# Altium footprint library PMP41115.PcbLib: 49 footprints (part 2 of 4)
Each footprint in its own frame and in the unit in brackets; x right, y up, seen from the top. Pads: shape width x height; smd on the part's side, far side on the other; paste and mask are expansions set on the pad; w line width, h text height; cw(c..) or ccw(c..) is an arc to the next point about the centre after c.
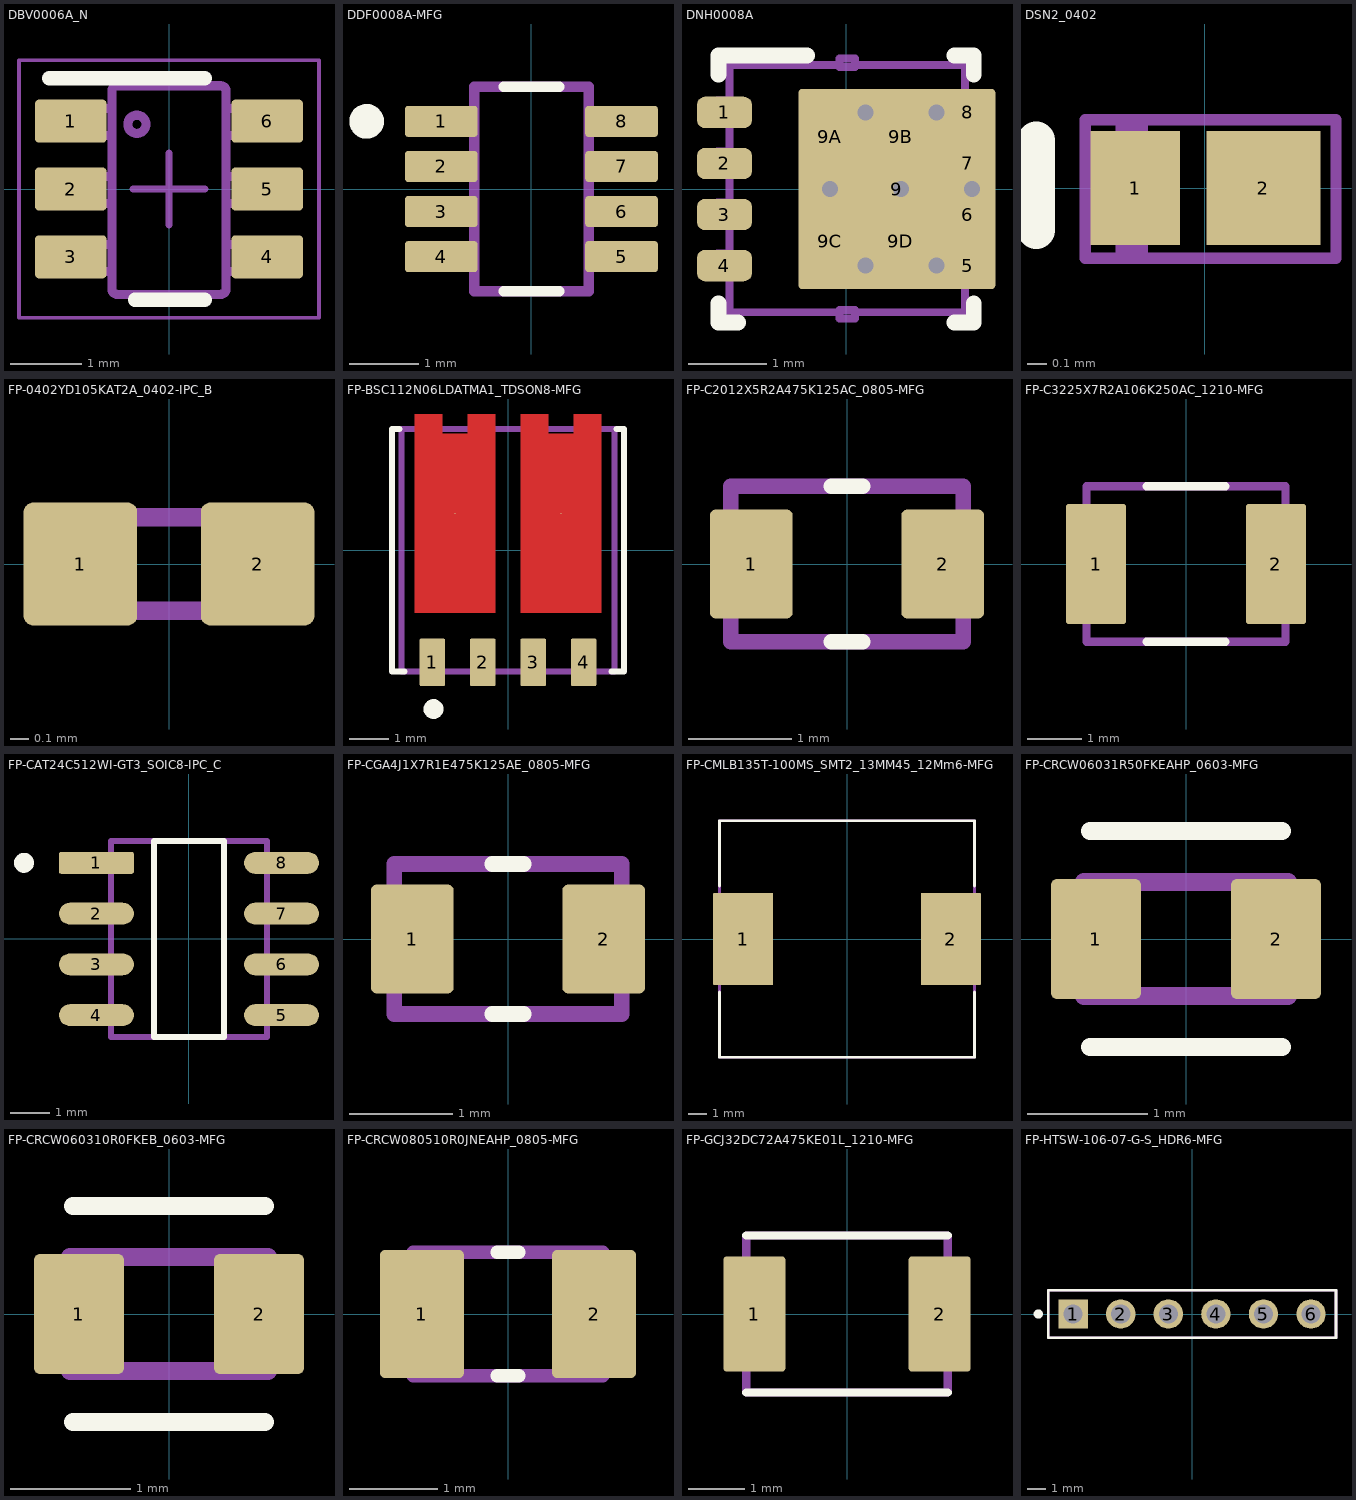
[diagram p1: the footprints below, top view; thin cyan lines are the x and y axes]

## DBV0006A_N [mm] "SOT23, 6-Leads, Body 2.9x1.6mm, Pitch 0.95mm, Lead Span 2.8mm, IPC Medium Density"
height 1.45
pads (6):
  rrect17% 1x0.6 smd: 1(-1.375,0.95) 2(-1.375,0) 3(-1.375,-0.95) 4(1.375,-0.95) 5(1.375,0) 6(1.375,0.95)
Top Overlay:
  lines w0.2: -1.675,1.55 0.5,1.55 ; -0.475,-1.55 0.5,-1.55
Mechanical 5:
  lines w0.127: 0.724,-1.475 ccw(c0.723,-1.399) 0.8,-1.399 0.8,1.37 ccw(c0.723,1.37) 0.724,1.446 ; 0.723,-1.475 -0.724,-1.475 -0.725,-1.475 cw(c-0.724,-1.399) -0.801,-1.399 -0.801,1.37 cw(c-0.724,1.37) -0.725,1.446 -0.724,1.446 0.723,1.446 ; 0.723,-1.475 0.724,-1.475 ; 0.723,1.446 0.724,1.446 ; -1.423,-1.154 -1.423,-0.78 -1.206,-0.78 -1.113,-0.78 -1.081,-0.78 -0.828,-0.78 -0.801,-0.78 -0.801,-1.154 -0.828,-1.154 -1.081,-1.154 -1.113,-1.154 -1.206,-1.154 -1.423,-1.154 ; -1.423,-0.202 -1.423,0.173 -1.206,0.173 -1.113,0.173 -1.081,0.173 -0.828,0.173 -0.801,0.173 -0.801,-0.202 -0.828,-0.202 -1.081,-0.202 -1.113,-0.202 -1.206,-0.202 -1.423,-0.202 ; -1.423,0.751 -1.423,1.125 -1.206,1.125 -1.113,1.125 -1.081,1.125 -0.828,1.125 -0.801,1.125 -0.801,0.751 -0.828,0.751 -1.081,0.751 -1.113,0.751 -1.206,0.751 -1.423,0.751 ; -0.577,0.906 ccw(c-0.45,0.906) -0.323,0.906 ccw(c-0.45,0.906) -0.577,0.906 ; 0.8,-1.154 0.8,-0.78 0.827,-0.78 1.08,-0.78 1.112,-0.78 1.205,-0.78 1.422,-0.78 1.422,-1.154 1.205,-1.154 1.112,-1.154 1.08,-1.154 0.827,-1.154 0.8,-1.154 ; 0.8,-0.202 0.8,0.173 0.827,0.173 1.08,0.173 1.112,0.173 1.205,0.173 1.422,0.173 1.422,-0.202 1.205,-0.202 1.112,-0.202 1.08,-0.202 0.827,-0.202 0.8,-0.202 ; 0.8,0.751 0.8,1.125 0.827,1.125 1.08,1.125 1.112,1.125 1.205,1.125 1.422,1.125 1.422,0.751 1.205,0.751 1.112,0.751 1.08,0.751 0.827,0.751 0.8,0.751
  text ".Designator" at -0.075,0.925 h0.51
Mechanical 15:
  lines w0.05: -2.1,-1.8 -2.1,1.8 2.1,1.8 2.1,-1.8 -2.1,-1.8
  lines w0.1: -0.5,0 0.5,0 ; 0,-0.5 0,0.5
3D body "DBV0006A.stp": height 1.12, standoff 0, extent -1.422,-1.461 1.423,1.46

## DDF0008A-MFG [mm]
height 1.1
pads (8):
  rrect22% 1.05x0.45 smd paste+0 mask+0: 1(-1.3,0.975) 2(-1.3,0.325) 3(-1.3,-0.325) 4(-1.3,-0.975) 5(1.3,-0.975) 6(1.3,-0.325) 7(1.3,0.325) 8(1.3,0.975)
Top Overlay:
  circle w0.25: c-2.375,0.975 r0.125
  lines w0.15: -0.4,-1.475 0.4,-1.475 ; -0.4,1.475 0.4,1.475
Mechanical 5:
  lines w0.15: -0.825,-1.475 0.825,-1.475 0.825,1.475 -0.825,1.475 -0.825,-1.475
  text ".Designator" at 0,0 h0.5
3D body "IC_LM74502DDF_SOT23-8.STEP": height 0.25, standoff 0, extent -1.925,-1.725 1.925,1.725

## DNH0008A [mm] "VSONP-8"
height 0.9
pads (13):
  rrect50% 0.7x0.4 smd paste-0.05 mask-0.05: 1(-1.55,0.975) 2(-1.55,0.325) 3(-1.55,-0.325) 4(-1.55,-0.975) 5(1.55,-0.975) 6(1.55,-0.325) 7(1.55,0.325) 8(1.55,0.975)
  rrect4% 2.51x2.55 smd paste-1.5 mask-1.5: 9(0.645,0)
  rrect50% 0.705x1.125 on Top Paste: 9A(-0.208,0.662) 9B(0.697,0.662) 9C(-0.208,-0.663) 9D(0.697,-0.663)
via 0.245,0.975 diameter 0.5 hole 0.2
via 1.15,0.975 diameter 0.5 hole 0.2
via 1.15,-0.975 diameter 0.5 hole 0.2
via 0.245,-0.975 diameter 0.5 hole 0.2
via 0.697,0 diameter 0.5 hole 0.2
via -0.208,0 diameter 0.5 hole 0.2
via 1.602,0 diameter 0.5 hole 0.2
Top Overlay:
  lines w0.2: -1.625,-1.453 -1.625,-1.7 -1.378,-1.7 ; -1.625,1.453 -1.625,1.7 -0.5,1.7 ; 1.378,-1.7 1.625,-1.7 1.625,-1.453 ; 1.378,1.7 1.625,1.7 1.625,1.453
Top Solder:
  region: -0.56,-1.175 -0.56,-1.185 -0.552,-1.203 -0.538,-1.217 -0.52,-1.225 -0.51,-1.225 1.165,-1.225 1.175,-1.225 1.193,-1.217 1.207,-1.203 1.215,-1.185 1.215,-1.175 1.215,-1.125 1.8,-1.125 1.81,-1.125 1.828,-1.117 1.842,-1.103 1.85,-1.085 1.85,-1.075 1.85,-0.875 1.85,-0.865 1.842,-0.847 1.828,-0.833 1.81,-0.825 1.8,-0.825 1.215,-0.825 1.215,-0.475 1.8,-0.475 1.81,-0.475 1.828,-0.467 1.842,-0.453 1.85,-0.435 1.85,-0.425 1.85,-0.225 1.85,-0.215 1.842,-0.197 1.828,-0.183 1.81,-0.175 1.8,-0.175 1.215,-0.175 1.215,0.175 1.8,0.175 1.81,0.175 1.828,0.183 1.842,0.197 1.85,0.215 1.85,0.225 1.85,0.425 1.85,0.435 1.842,0.453 1.828,0.467 1.81,0.475 1.8,0.475 1.215,0.475 1.215,0.825 1.8,0.825 1.81,0.825 1.828,0.833 1.842,0.847 1.85,0.865 1.85,0.875 1.85,1.075 1.85,1.085 1.842,1.103 1.828,1.117 1.81,1.125 1.8,1.125 1.215,1.125 1.215,1.175 1.215,1.185 1.207,1.203 1.193,1.217 1.175,1.225 1.165,1.225 -0.51,1.225 -0.52,1.225 -0.538,1.217 -0.552,1.203 -0.56,1.185 -0.56,1.175
Mechanical 5:
  lines w0.1: -1.487,-1.119 -1.487,-1.569 -0.087,-1.569 ; -1.487,-0.819 -1.487,-0.469 ; -1.487,-0.169 -1.487,0.181 ; -1.487,0.481 -1.487,0.831 ; -1.487,1.131 -1.487,1.581 -0.087,1.581 ; 0.113,-1.569 1.513,-1.569 1.513,-1.119 ; 0.113,1.581 1.513,1.581 1.513,1.131 ; 1.513,-0.819 1.513,-0.469 ; 1.513,-0.169 1.513,0.181 ; 1.513,0.481 1.513,0.831 ; -1.637,-1.119 -1.637,-0.819 -1.461,-0.819 -1.461,-1.119 -1.637,-1.119 ; -1.637,-0.469 -1.637,-0.169 -1.461,-0.169 -1.461,-0.469 -1.637,-0.469 ; -1.637,0.181 -1.461,0.181 -1.461,0.481 -1.637,0.481 -1.637,0.181 ; -1.637,0.831 -1.637,1.131 -1.461,1.131 -1.461,0.831 -1.637,0.831 ; -0.087,-1.649 -0.087,-1.543 0.113,-1.543 0.113,-1.649 -0.087,-1.649 ; -0.087,1.554 0.113,1.554 0.113,1.661 -0.087,1.661 -0.087,1.554 ; 1.486,-1.119 1.486,-0.819 1.663,-0.819 1.663,-1.119 1.486,-1.119 ; 1.486,-0.469 1.486,-0.169 1.663,-0.169 1.663,-0.469 1.486,-0.469 ; 1.486,0.181 1.486,0.481 1.663,0.481 1.663,0.181 1.486,0.181 ; 1.486,0.831 1.486,1.131 1.663,1.131 1.663,0.831 1.486,0.831
  text ".Designator" at -0.725,-0.165 h0.38
3D body "DNH0008A.stp": height 0.91, standoff 0.01, extent -1.65,-1.655 1.65,1.655

## DSN2_0402 [mm] "ON SEMICONDUCTOR"
height 0.31
pads (2):
  rect 0.47x0.6 smd: 1(-0.367,0)
  rect 0.6x0.6 smd: 2(0.308,0)
Top Overlay:
  lines w0.2: -0.89,-0.22 -0.89,0.25
Mechanical 5:
  lines w0.06: -0.44,-0.36 -0.44,0.35 ; -0.38,-0.36 -0.38,0.35 ; -0.33,-0.36 -0.33,0.35 ; -0.63,-0.37 -0.63,0.36 0.69,0.36 0.69,-0.37 -0.63,-0.37
  text ".Designator" at -0.26,-0.13 h0.24
3D body: height 0.32, standoff 0.31, extent -0.349,-0.299 -0.221,0.299
3D body: height 0.31, standoff 0, extent -0.499,-0.299 0.499,0.299

## FP-0402YD105KAT2A_0402-IPC_B [mm]
height 4.8
pads (2):
  rrect16% 0.608x0.658 smd paste+0 mask+0: 1(-0.475,0) 2(0.475,0)
Mechanical 5:
  lines w0.1: -0.5,-0.25 0.5,-0.25 0.5,0.25 -0.5,0.25 -0.5,-0.25
  text ".Designator" at 0,0 h0.5
3D body "Cap_0402YD105KAT2A_0402.STEP": height 0.56, standoff 0, extent -0.5,-0.25 0.5,0.25

## FP-BSC112N06LDATMA1_TDSON8-MFG [mm]
pads (6):
  rrect15% 0.65x1.2 smd paste+0 mask+0: 1(-1.905,-2.825) 2(-0.635,-2.825) 3(0.635,-2.825) 4(1.905,-2.825)
  round 0.025 smd: 5-6(1.332,0.925) 7-8(-1.333,0.925)
Top Layer:
  region: 2.35,3.425 1.65,3.425 1.65,2.925 1.015,2.925 1.015,3.425 0.315,3.425 0.315,-1.575 2.35,-1.575
  region: -2.35,3.425 -1.65,3.425 -1.65,2.925 -1.015,2.925 -1.015,3.425 -0.315,3.425 -0.315,-1.575 -2.35,-1.575
Top Overlay:
  circle w0.25: c-1.875,-4 r0.125
  lines w0.15: -2.725,3.05 -2.925,3.05 -2.925,-3.05 -2.605,-3.05 ; 2.605,-3.05 2.925,-3.05 2.925,3.05 2.725,3.05
Mechanical 5:
  lines w0.15: -2.675,-3.05 2.675,-3.05 2.675,3.05 -2.675,3.05 -2.675,-3.05
  text ".Designator" at 0.05,0.217 h0.5
3D body "Trans_BSC112N06LDATMA1_TDSON8.STEP": height 0.25, standoff 0, extent -2.895,-3.525 2.895,3.525

## FP-C2012X5R2A475K125AC_0805-MFG [mm]
height 1
pads (2):
  rrect13% 0.8x1.05 smd paste+0 mask+0: 1(-0.925,0) 2(0.925,0)
Top Overlay:
  lines w0.15: -0.15,-0.75 0.15,-0.75 ; -0.15,0.75 0.15,0.75
Mechanical 5:
  lines w0.15: -1.125,-0.75 1.125,-0.75 1.125,0.75 -1.125,0.75 -1.125,-0.75
  text ".Designator" at 0.05,0.217 h0.5
3D body "Cap_C2012X5R2A475K125AC_0805.STEP": height 0.25, standoff 0, extent -1.425,-0.85 1.425,0.85

## FP-C3225X7R2A106K250AC_1210-MFG [mm]
height 4.8
pads (2):
  rrect9% 1.1x2.2 smd paste+0 mask+0: 1(-1.65,0) 2(1.65,0)
Top Overlay:
  lines w0.15: -0.725,-1.425 0.725,-1.425 ; -0.725,1.425 0.725,1.425
Mechanical 5:
  lines w0.15: -1.825,-1.425 1.825,-1.425 1.825,1.425 -1.825,1.425 -1.825,-1.425
  text ".Designator" at 0.05,0.217 h0.5
3D body "Cap_C3225X7R2A106K250AC_1210.STEP": height 2.85, standoff 0, extent -1.6,-1.25 1.6,1.25

## FP-CAT24C512WI-GT3_SOIC8-IPC_C [mm]
height 4.8
pads (8):
  rrect18% 1.874x0.545 smd paste+0 mask+0: 1(-2.316,1.905)
  rrect100% 1.874x0.545 smd paste+0 mask+0: 2(-2.316,0.635) 3(-2.316,-0.635) 4(-2.316,-1.905) 5(2.316,-1.905) 6(2.316,-0.635) 7(2.316,0.635) 8(2.316,1.905)
Top Overlay:
  circle w0.25: c-4.128,1.905 r0.125
  lines w0.15: -0.879,-2.45 0.879,-2.45 0.879,2.45 -0.879,2.45 -0.879,-2.45
Mechanical 5:
  lines w0.15: -1.95,-2.45 1.95,-2.45 1.95,2.45 -1.95,2.45 -1.95,-2.45
  text ".Designator" at 0.05,0.217 h0.5
3D body "IC_CAT24C512WI-GT3_SOIC8.STEP": height 0.25, standoff 0, extent -3.353,-2.55 3.353,2.55

## FP-CGA4J1X7R1E475K125AE_0805-MFG [mm]
height 4.8
pads (2):
  rrect13% 0.8x1.05 smd paste+0 mask+0: 1(-0.925,0) 2(0.925,0)
Top Overlay:
  lines w0.15: -0.15,-0.725 0.15,-0.725 ; -0.15,0.725 0.15,0.725
Mechanical 5:
  lines w0.15: -1.1,-0.725 1.1,-0.725 1.1,0.725 -1.1,0.725 -1.1,-0.725
  text ".Designator" at 0.05,0.217 h0.5
3D body "Cap_CGA4J1X7R1E475K125AE_0805.STEP": height 0.25, standoff 0, extent -1.425,-0.825 1.425,0.825

## FP-CMLB135T-100MS_SMT2_13MM45_12Mm6-MFG [mm]
height 4.8
pads (2):
  rrect3% 3.25x5 smd paste+0 mask+0: 1(-5.625,0) 2(5.625,0)
Top Overlay:
  lines w0.15: -6.9,-2.875 -6.9,-6.4 6.9,-6.4 6.9,-2.875 ; -6.9,2.875 -6.9,6.4 6.9,6.4 6.9,2.875
Mechanical 5:
  lines w0.15: -6.9,-6.4 -6.9,6.4 6.9,6.4 6.9,-6.4 -6.9,-6.4
  text ".Designator" at 0.05,0.217 h0.5
3D body "Ind_CMLB135T-100MS_SMT2_13MM45_12Mm6.STEP": height 0.25, standoff 0, extent -7.35,-6.5 7.35,6.5

## FP-CRCW06031R50FKEAHP_0603-MFG [mm]
height 1.1
pads (2):
  rrect13% 0.75x1 smd paste+0 mask+0: 1(-0.75,0) 2(0.75,0)
Top Overlay:
  lines w0.15: -0.8,-0.9 0.8,-0.9 ; -0.8,0.9 0.8,0.9
Mechanical 5:
  lines w0.15: -0.85,-0.475 -0.85,0.475 0.85,0.475 0.85,-0.475 -0.85,-0.475
  text ".Designator" at 0.05,0.217 h0.5
3D body "Res_CRCW06031R50FKEAHP_0603.STEP": height 0.25, standoff 0, extent -1.225,-0.6 1.225,0.6

## FP-CRCW060310R0FKEB_0603-MFG [mm]
height 4.8
pads (2):
  rrect13% 0.75x1 smd paste+0 mask+0: 1(-0.75,0) 2(0.75,0)
Top Overlay:
  lines w0.15: -0.8,-0.9 0.8,-0.9 ; -0.8,0.9 0.8,0.9
Mechanical 5:
  lines w0.15: -0.825,-0.475 0.825,-0.475 0.825,0.475 -0.825,0.475 -0.825,-0.475
  text ".Designator" at 0.05,0.217 h0.5
3D body "Res_CRCW060310R0FKEB_0603.STEP": height 0.25, standoff 0, extent -1.225,-0.6 1.225,0.6

## FP-CRCW080510R0JNEAHP_0805-MFG [mm]
height 4.8
pads (2):
  rrect11% 0.95x1.45 smd paste+0 mask+0: 1(-0.975,0) 2(0.975,0)
Top Overlay:
  lines w0.15: -0.125,-0.7 0.125,-0.7 ; -0.125,0.7 0.125,0.7
Mechanical 5:
  lines w0.15: -1.075,-0.7 1.075,-0.7 1.075,0.7 -1.075,0.7 -1.075,-0.7
  text ".Designator" at 0.05,0.217 h0.5
3D body "Res_CRCW080510R0JNEAHP_0805.STEP": height 0.25, standoff 0, extent -1.55,-0.825 1.55,0.825

## FP-GCJ32DC72A475KE01L_1210-MFG [mm]
height 4.8
pads (2):
  rrect9% 1.1x2.05 smd paste+0 mask+0: 1(-1.65,0) 2(1.65,0)
Top Overlay:
  lines w0.15: -1.8,-1.4 1.8,-1.4 ; -1.8,1.4 1.8,1.4
Mechanical 5:
  lines w0.15: -1.8,-1.4 -1.8,1.4 1.8,1.4 1.8,-1.4 -1.8,-1.4
  text ".Designator" at 0.05,0.217 h0.5
3D body "Cap_GCJ32DC72A475KE01L_1210.STEP": height 2.3, standoff 0, extent -1.6,-1.25 1.6,1.25

## FP-HTSW-106-07-G-S_HDR6-MFG [mm]
height 10.287
pads (6):
  rrect6% 1.57x1.57 hole 1.02 paste-1000 mask+0: 1(-6.35,0)
  round 1.57 hole 1.02 paste-1000 mask+0: 2(-3.81,0) 3(-1.27,0) 4(1.27,0) 5(3.81,0) 6(6.35,0)
Top Overlay:
  circle w0.25: c-8.21,0 r0.125
  lines w0.15: -7.683,-1.27 -7.683,1.27 7.683,1.27 7.683,-1.27 -7.683,-1.27
Mechanical 5:
  lines w0.15: -7.683,-1.27 -7.683,1.27 7.683,1.27 7.683,-1.27 -7.683,-1.27
  text ".Designator" at 0.05,0.217 h0.5
3D body "Conn_HTSW-106-07-G-S_HDR6.STEP": height 0.25, standoff 0, extent -7.783,-1.37 7.783,1.37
